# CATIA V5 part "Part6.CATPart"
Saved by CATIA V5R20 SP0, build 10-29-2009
Part number: 9FP1406M5
Revision: ANY
Definition: UNKNOWN
Nomenclature: 9FP1406M5
Source: Unknown
Bounding box of the stored display mesh (mm): x -6.727 to 6.727, y 0 to 6, z -6.9 to 6.9
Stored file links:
  C:\Users\Utente\Desktop\IO LAVORO\3D X SITO CF\CUMSA\3D files PW\pw081025\pw081025_injection\Part6.CATPart
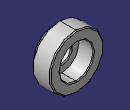
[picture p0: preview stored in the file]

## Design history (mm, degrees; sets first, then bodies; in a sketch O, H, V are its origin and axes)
Body1 "Chaflán1" (main body)
  Solid1: solid without history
